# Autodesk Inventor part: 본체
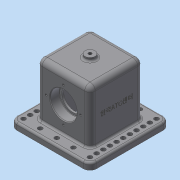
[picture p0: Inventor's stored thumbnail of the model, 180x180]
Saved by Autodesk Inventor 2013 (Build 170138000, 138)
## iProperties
Created: 2018-11
Part Number: 본체
Material: Generic
Document SubType Name: Modeling
Designer: Administrator
Density: 1 g/cm^3
Author: Administrator
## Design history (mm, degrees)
sketch "스케치1"
  geometry: 1 further point
sketch "스케치2"
  geometry: L1 (-60, 60)-(60, 60); L2 (60, 60)-(60, -60); L3 (60, -60)-(-60, -60); L4 (-60, -60)-(-60, 60); 3 further points
  constraints: 8 end point, 2 midpoint, 2 parallel, 1 horizontal, 1 horizontal alignment, 1 perpendicular, 1 vertical alignment
  dimensions: "d7" = 120 distance of L1.end L2.end; "d9" = 120 distance of L1.start L1.end
extrude "돌출1" new body sketch "스케치2" distance "d10" = 10; taper "d11" = 0 deg
fillet "모깎기1" dims "d12" = 10
sketch "스케치3"
  geometry: L1 (-40, 40)-(40, 40); L2 (40, 40)-(40, -40); L3 (40, -40)-(-40, -40); L4 (-40, -40)-(-40, 40); 3 further points
  constraints: 8 end point, 2 midpoint, 2 parallel, 1 horizontal, 1 horizontal alignment, 1 perpendicular, 1 vertical alignment
  dimensions: "d13" = 80 distance of L1.start L1.end; "d15" = 80 distance of L1.end L2.end
extrude "돌출2" join sketch "스케치3" distance "d16" = 80; taper "d17" = 0 deg
fillet "모깎기2" dims "d18" = 8
sketch "스케치4"
  geometry: L1 (30, -23)-(-30, -23); L2 (-30, -23)-(-30, 23); L3 (-30, 23)-(30, 23); L4 (30, 23)-(30, -23); 3 further points
  constraints: 8 end point, 2 midpoint, 2 parallel, 1 horizontal, 1 horizontal alignment, 1 perpendicular, 1 vertical alignment
  dimensions: "d19" = 60 distance of L1.start L1.end; "d21" = 46 distance of L1.end L2.end
extrude "돌출3" cut sketch "스케치4" distance "d22" = 80; taper "d23" = 0 deg
sketch "스케치5"
  geometry: C1 r 7.5 at (0, 0); 1 further point
  constraints: 1 centre point, 1 coincident
  dimensions: "d24" = 15 diameter of C1
extrude "돌출4" join sketch "스케치5" distance "d26" = 5; taper "d27" = 0 deg
fillet "모깎기3" dims "d28" = 8
sketch "스케치6"
  geometry: 1 further point
sketch "스케치7"
  geometry: L1 (40, 48)-(-40, 48); L2 (-40, 48)-(-40, 28); L3 (-40, 28)-(-26, 28); L4 (-26, 28)-(-26, 31.5); L5 (-26, 31.5)-(26, 31.5); L6 (26, 31.5)-(26, 28); L7 (26, 28)-(40, 28); L8 (40, 28)-(40, 48); L9 (40, 82)-(40, 10) reference; L10 (-40, 10)-(-40, 82) reference; L11 (23, 0)-(23, 80) reference; L12 (-23, 0)-(-23, 80) reference; L13 (-50, 0)-(50, 0) reference; 1 further point
  constraints: 16 end point, 6 parallel, 2 vertical alignment, 1 horizontal, 1 perpendicular
  dimensions: "d29" = 14 distance of L2.end L3.end; "d31" = 14 distance of L6.end L7.end; "d32" = 40 diameter of L7 L1; "d33" = 40 diameter of L3 L1; "d34" = 33 diameter of L5 L1; "d35" = 48 distance between parallel lines of L1 L13
revolve "회전1" sketch "스케치7" stored, may be unused: angle "d36" = 90 deg
chamfer "모따기1" distance "d37" = 1; stored, may be unused: second distance "d38" = 2, angle "d39" = 45 deg
fillet "모깎기4" dims "d40" = 0.6
sketch "스케치8"
  geometry: C1 r 21 at (32, 38) reference; 2 further points
  constraints: 1 vertical alignment
  dimensions: "d41" = 26 distance of point (32, 64) C1.centre
hole "구멍1" sketch "스케치8" at (32, 64) diameter "d42" = 3.242; stored, may be unused: countersink angle "d46" = 90 deg, drill point angle "d48" = 118 deg; dims "d43" = 8, "d44" = 4, "d45" = 2, "d47" = 10
hole "구멍2" diameter "d54" = 4.917; stored, may be unused: countersink angle "d58" = 90 deg, drill point angle "d60" = 118 deg; dims "d52" = 10, "d53" = 10, "d55" = 8, "d56" = 4, "d57" = 2, "d59" = 10
sketch "스케치9"
  geometry: A1 r 10 centre (-50, 50) between (-50, 60) and (-60, 50) reference; 1 further point
hole "구멍3" sketch "스케치9" at (-50, 50) diameter "d61" = 6.6; stored, may be unused: countersink angle "d65" = 90 deg, drill point angle "d67" = 118 deg; dims "d62" = 8, "d63" = 4, "d64" = 2, "d66" = 10
fillet "모깎기5" dims "d80" = 3
fillet "모깎기6" dims "d81" = 3
sketch "스케치10"
  geometry: L1 (0, 0)-(0, 64) reference; L2 (82, 82)-(82, -18) reference; 4 further points
  constraints: 2 horizontal alignment, 2 midpoint, 1 other
  dimensions: "d82" = 48 distance from line of L2 point (34, 32)
feature "엠보싱1" sketch "스케치10" dims "d7" = 120, "d9" = 120, "d83" = 0.5, "d84" = 0
node "솔리드1"
pattern_circular "원형 패턴1" dims angle "d50" = 360 deg
mirror "대칭1"
pattern_linear "직사각형 패턴3" dims "d76" = 10
mirror "대칭4"
pattern_linear "직사각형 패턴4" dims "d79" = 25
mirror "대칭5"
